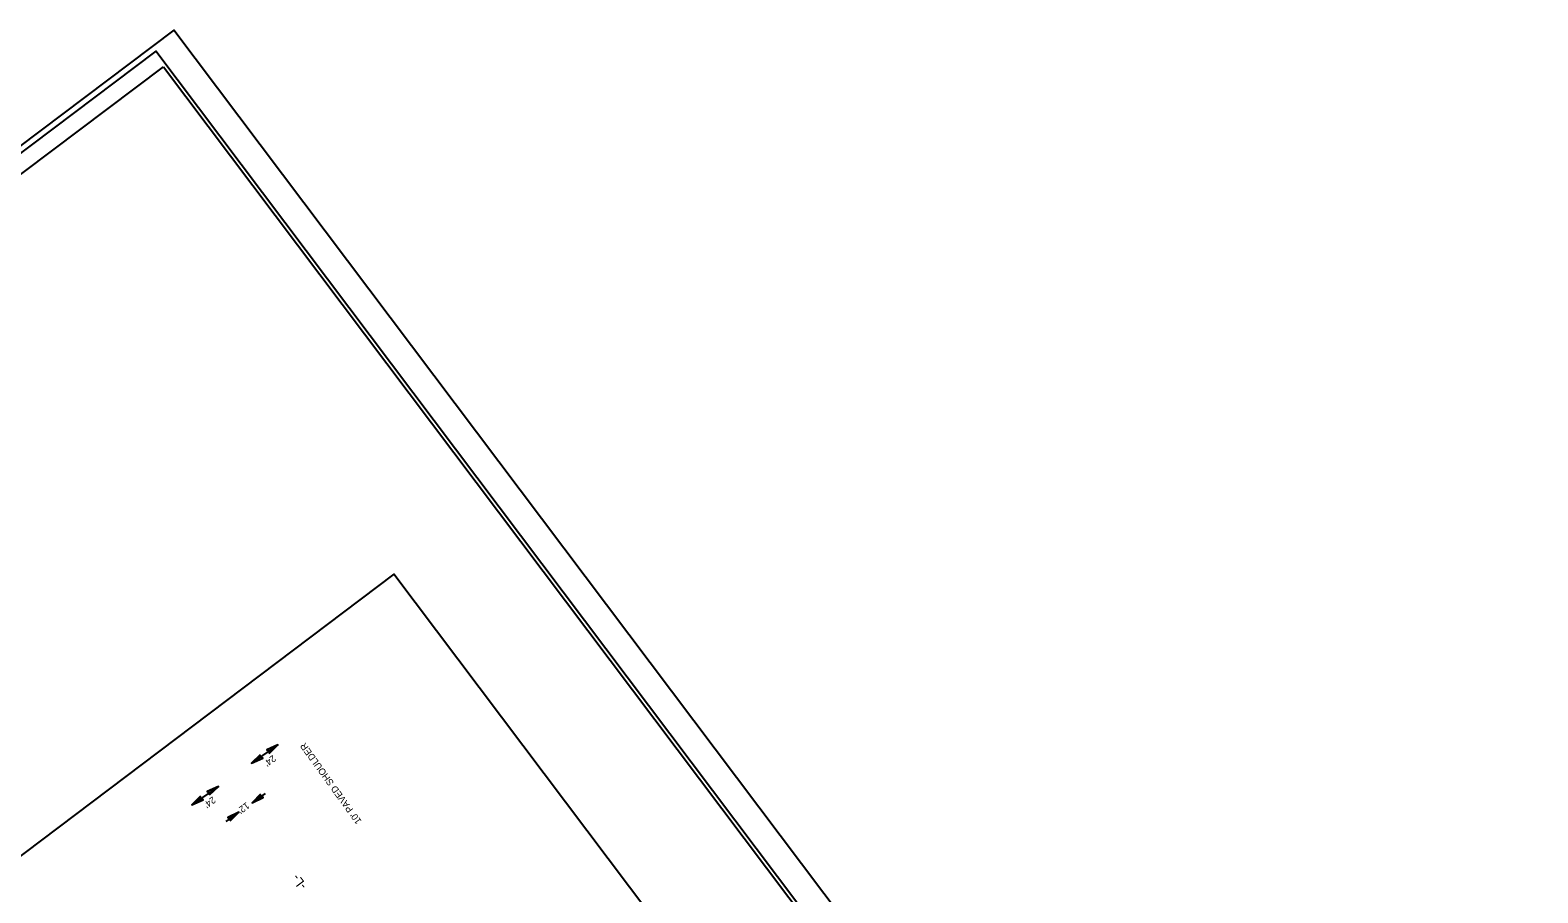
# Model space of a CAD drawing. Extents: x 1262917 to 1264804, y 775326 to 777329.
# Drawn here: x 1263684 to 1264804, y 776689 to 777329 of the extents above; entities that cross this region are included whole.
import ezdxf

# ---------------------------------------------------------------- set-up
doc = ezdxf.new("R2010")
doc.units = 0
for name, color, linetype in [('Prop Dimension Text', 7, 'Continuous'), ('Prop Horizontal Alignment Direction Label', 7, 'Continuous'), ('Prop Terminator CELL', 7, 'Continuous'), ('Sheet Plot Border Inside CELL', 7, 'Continuous'), ('Sheet Plot Border Outside CELL', 7, 'Continuous'), ('Sheet Typical CELL', 7, 'Continuous')]:
    doc.layers.add(name, color=color, linetype=linetype)

msp = doc.modelspace()

# ---------------------------------------------------------------- linework, layer by layer
at = {"layer": 'Prop Dimension Text'}
for p, q in [((1263868.5, 776798.8), (1263848.8, 776785.1)), ((1263824.2, 776768), (1263804.5, 776754.3)), ((1263858.9, 776762.8), (1263849.2, 776755.8)), ((1263839.4, 776748.8), (1263829.7, 776741.8))]:
    msp.add_line(p, q, dxfattribs=at)
at = {"layer": 'Prop Terminator CELL'}
for points in [[(1263855.3, 776791.5), (1263848.8, 776785.1), (1263857.2, 776789), (1263855.3, 776789.6)], [(1263862, 776792.4), (1263868.5, 776798.8), (1263860.2, 776795), (1263862.1, 776794.3)], [(1263811, 776760.7), (1263804.5, 776754.3), (1263812.9, 776758.1), (1263811, 776758.8)], [(1263817.7, 776761.6), (1263824.2, 776768), (1263815.9, 776764.1), (1263817.7, 776763.5)], [(1263855.6, 776762.3), (1263849.2, 776755.8), (1263857.5, 776759.8), (1263855.6, 776760.4)], [(1263833, 776742.3), (1263839.4, 776748.8), (1263831.2, 776744.8), (1263833, 776744.2)]]:
    msp.add_lwpolyline(points, close=True, dxfattribs=at)
at = {"layer": 'Sheet Plot Border Inside CELL'}
msp.add_lwpolyline([(1264780.2, 775982.9), (1263777.9, 777313.6), (1262935.2, 776678.9), (1263937.5, 775348.2)], close=True, dxfattribs=at)
at = {"layer": 'Sheet Plot Border Outside CELL'}
msp.add_lwpolyline([(1262916.5, 776670.5), (1263929.4, 775325.7), (1264804, 775984.5), (1263791.2, 777329.3)], close=True, dxfattribs=at)
at = {"layer": 'Sheet Typical CELL'}
for p, q in [((1262944.7, 776670.4), (1263783.4, 777302.1)), ((1263783.4, 777302.1), (1264685.9, 776104))]:
    msp.add_line(p, q, dxfattribs=at)
msp.add_lwpolyline([(1264496.1, 776206.6), (1263954.6, 776925.5), (1263643.1, 776690.8), (1264184.6, 775972)], close=True, dxfattribs=at)

# ---------------------------------------------------------------- texts
at = {"layer": 'Prop Dimension Text'}
for s, rotation, p in [("24'", 216.9874, (1263864.6, 776791.5)), ("10' PAVED SHOULDER", 125.7526, (1263930.8, 776742.2)), ("24'", 216.9874, (1263819.9, 776760.7)), ("12'", 216.9874, (1263845, 776756.5))]:
    msp.add_text(s, height=5, rotation=rotation, dxfattribs=at).set_placement(p)
at = {"layer": 'Prop Horizontal Alignment Direction Label'}
msp.add_text('-L-', height=7, rotation=126.9852, dxfattribs=at).set_placement((1263890.3, 776694.4))

doc.saveas('drawing.dxf')
